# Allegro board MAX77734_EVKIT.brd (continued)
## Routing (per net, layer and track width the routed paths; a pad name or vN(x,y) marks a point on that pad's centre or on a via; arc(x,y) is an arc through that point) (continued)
UNNAMED_4_EKRESSMD_I17_2: length 1.6
  TOP w0.254: v1(15.5,63.17) 15.85,62.82 D100.K
  BOTTOM w0.254: R111.2 v1(15.5,63.17)
UNNAMED_4_EKRESSMD_I18_1: length 1.6
  BOTTOM w0.254: R109.1 14.45,61.28 14.18,61.02 U101.21
UNNAMED_4_EKRESSMD_I18_2: length 1.7
  TOP w0.254: v1(14.58,63.2) 14.58,63.14 14.28,62.83 D101.K
  BOTTOM w0.254: R109.2 14.45,63.06 v1(14.58,63.2)
UNNAMED_4_EKRESSMD_I87_1: length 2.5
  BOTTOM w0.254: R150.1 49.58,57.46 49.55,57.44 48.88,57.44 48.4,57.92 U107.3
UNNAMED_4_EKRESSMD_I109_1: length 1.9
  BOTTOM w0.254: R155.1 21.19,51.43 21.66,50.96 21.66,50.84 22.04,50.47 U100.36
UNNAMED_4_EKRESSMD_I113_1: length 1.7
  BOTTOM w0.254: R148.1 22.08,51.11 22.26,50.93 22.26,50.88 22.54,50.61 U100.37
UNNAMED_4_EKRESSMD_I153_1: length 1.8
  BOTTOM w0.254: U107.1 49.43,60.08 49.57,59.95 R135.1
UNNAMED_4_EKRESSMD_I154_1: length 1.8
  BOTTOM w0.254: R136.1 49.58,59.2 49.5,59.28 U107.2
UNNAMED_4_EKRESSMD_I171_2: length 1.7
  BOTTOM w0.254: U107.6 45.7,56.36 45.7,56.36 R143.2
UNNAMED_4_EKRESSMD_I174_1: length 2.5
  BOTTOM w0.381: R157.1 30.23,48.07 R156.2 30.26,48.06 30.96,48.06 31.33,48.43 U104.4
UNNAMED_4_EKRESSMD_I177_1: length 2.8
  BOTTOM w0.254: R159.1 20.69,57.08 R158.2 21.88,57.09 22.14,57.35 U102.4
UNNAMED_4_EKRESSMD_I190_2: length 2.7
  BOTTOM w0.254: U107.8 43.5,59.28 43.46,59.32 R151.2 42.88,60.22 R152.2
UNNAMED_4_EKRESSMD_I210_1: length 1.6
  BOTTOM w0.254: R133.1 47.3,55.96 47.3,55.97 U107.4
UNNAMED_4_LED_I7_B: length 1.7
  TOP w0.254: D102.K 20.38,62.83 20.41,62.86 R110.1
UNNAMED_4_LED_I189_B: length 38.8
  TOP w0.254: D103.K 63.05,43.5 v1(64.37,43.5) ; v1(41.96,57.49) 57.77,57.49 59.17,56.1 v1(64.37,56.1)
  INTERNAL3 w0.254: v1(64.37,56.1) v1(64.37,43.5)
  BOTTOM w0.254: v1(41.96,57.49) 41.96,58.1 41.98,58.12 R151.1
UNNAMED_4_MAX8512_I5_FB: length 2.6
  BOTTOM w0.254: U103.4 32.6,55.6 31.76,55.6 31.41,55.25 R160.2 31.29,55.25 R161.1
UNNAMED_6_CAPNP_I245_2: length 3.2
  BOTTOM w0.254: U209.1 56.62,25.49 C249.2 56.85,26.51 R285.2
UNNAMED_6_CAPNP_I341_2: length 5.2
  BOTTOM w0.203: U203.5 65.48,14.39 R252.2 65.3,15.42 C218.2 65.31,16.46 R254.1 64.96,16.81 R299.1
UNNAMED_6_CAPNP_I345_1: length 16
  INTERNAL3 w0.254: v1(67.95,14.54) 67.95,8.12 64.96,5.13 v1(64.96,3.93)
  BOTTOM w0.203: R253.1 67.2,15.41 C219.1 67.2,14.34 66.78,13.92 U203.7
  BOTTOM w0.254: R249.2 64.96,4.58 v1(64.96,3.93) ; C219.1 v1(67.95,14.54)
UNNAMED_6_CAPNP_I345_2: length 5.1
  BOTTOM w0.203: R300.2 66.45,16.77 R255.1 66.43,16.24 66.3,16.11 R253.2 66.3,15.41 C219.2 66.13,14.37 U203.6
UNNAMED_6_CAPNP_I357_2: length 4.2
  BOTTOM w0.203: R250.2 64.09,5.5 64.09,5.79 64.35,6.05 C251.2 65.08,6.39 65.12,6.36 65.54,6.36 66.13,6.95 U203.3
UNNAMED_6_EKCAPNP_I203_2: length 2.1
  BOTTOM w0.254: U205.10 48.74,11.62 C223.2
UNNAMED_6_EKCAPNP_I214_2: length 3.2
  BOTTOM w0.254: U209.8 48.75,25.49 48.44,25.8 C237.2 46.97,25.8 R286.2
UNNAMED_6_EKCAPNP_I332_2: length 18.9
  TOP w0.254: v1(70.06,26.95) 59.2,26.95 58.73,27.42 v1(57.49,27.42)
  INTERNAL3 w0.254: v1(57.49,27.42) 57.49,24.66 57.96,24.19 v1(57.96,22.15)
  BOTTOM w0.254: R259.1 v1(57.96,22.15)
  vias: v1(71.45,26.19) v1(72.74,26.18) v1(74.33,26.12)
UNNAMED_6_EKCAPNP_I355_1: length 3.9
  BOTTOM w0.203: R249.1 64.97,5.48 C216.1 65.84,5.48 66.78,6.42 U203.2
UNNAMED_6_EKCAPNP_I355_2: length 1
  BOTTOM w0.203: R248.1 65.8,4.57 C216.2
UNNAMED_6_EKCAPNP_I456_2: length 4.1
  BOTTOM w0.254: C235.2 49.62,18.39 U210.5 51.1,19.71 51.88,20.49 R279.1
UNNAMED_6_EKCAPNP_I459_2: length 7.1
  BOTTOM w0.254: C234.2 52.22,13.9 R280.1 51.64,14.97 51.08,15.52 51.08,16.48 U210.4 50.09,16.49 50.08,16.48 48.87,16.48 48.36,16.99 R277.2
UNNAMED_6_EKRESSMD_I207_2: length 1.9
  BOTTOM w0.254: U205.2 56.4,11.12 56.48,11.2 R214.2
UNNAMED_6_EKRESSMD_I222_2: length 2.1
  BOTTOM w0.254: U205.1 56,11.62 56.42,12.04 56.46,12.04 56.47,12.05 R283.2
UNNAMED_6_EKRESSMD_I340_2: length 8.9
  TOP w0.203: v1(70.35,18.79) 65.74,18.79 65.57,18.63 v1(64.99,18.63)
  BOTTOM w0.203: R254.2 64.98,18.61 v1(64.99,18.63) ; v1(70.35,18.79) 70.35,19.94 70.57,20.16 R258.1
UNNAMED_6_EKRESSMD_I347_1: length 3.7
  BOTTOM w0.203: U203.1 67.43,6.35 67.75,6.03 R251.1 67.74,5.47 R248.2
UNNAMED_6_EKRESSMD_I347_2: length 7.9
  BOTTOM w0.203: J206.1 72.14,8.36 68.35,4.58 R251.2
UNNAMED_6_EKRESSMD_I450_2: length 2.3
  BOTTOM w0.254: R213.2 57.04,9.3 56.36,9.98 56.3,9.98 56.16,10.12 U205.4
UNNAMED_6_EKRESSMD_I451_2: length 2.7
  BOTTOM w0.254: U205.5 55.15,9.09 55.87,8.38 R212.2
UNNAMED_6_EKRESSMD_I452_2: length 2.2
  BOTTOM w0.254: U209.6 48.65,24.19 48.43,23.98 R303.2
UNNAMED_6_EKRESSMD_I453_2: length 2.3
  BOTTOM w0.254: U209.5 48.78,23.54 48.43,23.19 47.94,23.19 R304.2
UNNAMED_6_EKRESSMD_I460_2: length 1.9
  BOTTOM w0.254: R280.2 53.12,15.02 54,15.9 U210.3
UNNAMED_6_EKRESSMD_I469_2: length 2.1
  BOTTOM w0.254: U205.3 56.68,10.62 R211.2
UNNAMED_6_EKRESSMD_I472_1: length 2
  BOTTOM w0.254: R210.1 49.06,10.97 49.22,11.12 U205.9
UNNAMED_6_EKRESSMD_I472_2: length 23.7
  TOP w0.254: v1(47.18,10.97) v1(63.15,10.97)
  INTERNAL3 w0.254: v1(63.15,10.97) v1(63.15,4.61)
  BOTTOM w0.254: v1(63.15,4.61) 64.08,4.61 R250.1 ; R210.2 v1(47.18,10.97)
UNNAMED_6_HEADER2P_I448_2: length 17.7
  INTERNAL3 w0.254: v1(71.28,11.02) 71.28,21.4 v1(70.43,22.25)
  BOTTOM w0.254: Q203.4 70.48,22.29 v1(70.43,22.25) ; R257.1 74.13,12.96 74.08,12.91 J206.2 72.82,10.9 72.7,11.02 v1(71.28,11.02)
UNNAMED_6_RESSMD_I363_2: length 5
  BOTTOM w0.254: R288.2 41.09,18.22 41.75,17.56 Q205.1 43.1,15.63 43.09,15.63 Q206.3
VADC: length 15.1
  INTERNAL3 w0.254: v1(45.2,25.76) v1(45.2,19.52)
  BOTTOM w0.254: R277.1 47.57,19.05 47.16,19.46 45.62,19.46 ; 45.62,19.46 45.55,19.52 v1(45.2,19.52) ; 45.62,19.46 Q205.2 41.44,19.46 41.09,19.12 R288.1 ; R286.1 v1(45.2,25.76)
VIO: length 157.9
  TOP w0.254: R9.1 62.97,39.2 62.97,39.2 v1(62,39.2) ; v1(44.8,55.16) v1(36.19,55.16)
  TOP w0.381: R6.1 29.82,62.94 30.3,62.46 v1(36.09,62.46) ; v1(41,34.55) 41.53,34.55 C5.2 41.58,34.55 60.93,34.55 61.06,34.68 v1(62,34.68) ; VIO.1 65.59,50.4 65.51,50.48 v1(62,50.48) v1(49.5,50.48) v1(36.14,50.48)
  TOP w0.508: J2.1 36.88,74.09 16.46,74.09 J101.1 J101.3 J101.5
  INTERNAL3 w0.203: v1(41,34.55) 40.08,34.55 v2(39.54,35.1)
  INTERNAL3 w0.254: v1(49.56,60.69) 49.56,59.04 49.5,58.98 v1(49.5,58.37) ; 36.14,55.18 36.16,55.16 v1(36.19,55.16)
  INTERNAL3 w0.381: v1(36.14,50.48) 36.14,62.53 ; 36.14,62.53 36.14,65.22 38.74,67.82 J2.1 ; 36.14,62.53 36.09,62.48 v1(36.09,62.46) ; v1(62,34.68) v1(62,39.2) v1(62,50.48) ; v1(49.5,58.37) v1(49.5,50.48)
  BOTTOM w0.254: R108.1 v1(49.56,60.69) ; R143.1 v1(44.8,55.16) ; R107.1 49.77,58.37 49.77,58.37 v1(49.5,58.37)
  BOTTOM w0.381: 47.91,61.18 U107.12 ; 47.91,61.18 48.41,60.69 v1(49.56,60.69) ; 47.91,61.18 48.65,61.91 C120.2
VL: length 55.2
  TOP w0.203: U1.A2 38.74,36.34 39.58,37.18 39.58,37.45 C3.2 v1(39.71,38.31)
  INTERNAL3 w0.381: v1(39.71,38.31) v1(39.71,65.98) ; VL.1 v1(21.1,65.98)
  BOTTOM w0.381: v1(39.71,65.98) 38.89,65.98 38.88,65.98 v1(21.1,65.98)
VUSB: length 196.8
  TOP w0.381: v1(48.15,15.59) 60.68,15.59 v1(63.11,13.16) v1(69.84,13.16)
  TOP w0.508: v1(47.9,41.42) v1(63.16,41.42) ; v1(12.13,61.84) 12.87,61.84 13.32,61.38 v1(26.39,61.38) 27.13,61.38 27.18,61.43 v1(36.95,61.43)
  TOP w0.635: v1(8.84,60.36) 9.85,60.36 11.33,61.84 v1(12.13,61.84)
  INTERNAL3 w0.381: v1(47.9,49.73) 47.9,49.35 47.9,49.35 ; v1(36.95,57.8) v1(36.95,49.73)
  INTERNAL3 w0.508: J100.1 49.84,66.39 47.9,64.45 v1(47.9,41.42) ; v1(63.16,41.42) 63.16,20.34 62.59,19.77 62.59,13.68 v1(63.11,13.16) ; v1(36.95,57.8) v1(36.95,61.43)
  INTERNAL3 w0.635: v1(8.84,60.36) 8.84,57.61 8.01,56.78 v1(8.01,54.63)
  BOTTOM w0.254: U203.8 68.27,12.81 68.64,13.18 C217.1 ; U103.3 34.4,55.68 34.07,56.01 34.07,56.84 34.21,56.98 U103.1 ; C110.2 v1(36.95,57.8) ; U101.19 13.18,60.75 12.66,61.27 C108.2 v1(12.13,61.84) ; Q205.3 45.3,16.58 45.29,16.58 Q206.1 47.05,15.87 R287.1
  BOTTOM w0.381: FB100.2 8.01,55.56 v1(8.01,54.63) C154.2 8.04,53.92 R115.1 8.04,52.18 ; v1(47.9,49.73) v1(36.95,49.73) 36.19,49.73 C112.2 35.49,49.74 35.48,49.73 U104.1 34.06,49.81 33.19,49.81 32.92,49.54 32.92,48.7 33.19,48.43 U104.3 ; U103.1 36.2,56.98 36.25,57.03 C110.2 ; R287.1 v1(48.15,15.59) ; C217.1 69.69,13.18 69.71,13.16 v1(69.84,13.16) ; U102.3 23.58,57.83 23.31,58.1 23.31,58.88 23.58,59.15 24.51,59.15 U102.1 25.53,59.13 25.55,59.11 C118.2 26.33,60.65 26.39,60.71 v1(26.39,61.38)
  BOTTOM w1.016: 8.04,52.18 8.04,50.43 6.78,49.18 5.36,49.18 5.35,49.19 J3.2

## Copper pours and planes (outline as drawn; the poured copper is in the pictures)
BATT on TOP: 3.43,20.95 3.68,20.7 24.51,20.7 35.81,32 35.81,33.78 36.2,34.16 37.08,34.16 37.21,34.29 37.21,34.67 35.31,34.67 27.81,27.18 21.34,27.18 19.18,25.02 3.43,25.02
BATTN on TOP: 3.81,10.79 3.81,19.18 4.7,20.07 15.37,20.07 15.49,19.94 15.49,17.14 9.14,10.79
CHGIN on TOP: 10.16,33.15 6.84,36.53 6.84,36.61 8.02,37.8 10.35,37.8 12.05,39.49 12.83,40.26 35.05,40.26 36.2,39.12 37.06,38.27 37.43,37.89 37.44,37.4 37.89,36.94 38.32,36.52 38.33,36.37 38.32,35.96 37.82,35.96 37.35,35.96 37.11,36.19 37.1,36.95 36.8,37.25 36.46,37.25 31.72,37.23 27.56,33.15
GROUND on TOP: 1.14,1.27 1.14,75.18 75.56,75.18 75.56,1.27 ; 19 cut-outs
GROUND on BOTTOM: 1.27,75.44 1.27,0.51 75.44,0.51 75.44,75.31 ; 14 cut-outs
GROUND on INTERNAL2: 0.89,75.18 0.89,0.89 75.95,0.89 75.95,75.18
INLDO on TOP: 42.45,2.8 42.45,12.07 39.01,15.51 39.01,31.86 39.03,31.88 39.02,32.81 39.02,33.39 39.22,33.57 39.45,33.79 39.45,34.52 39.56,34.62 39.67,34.51 39.67,33.19 39.66,31.37 39.66,31.37 39.66,29.98 40.65,28.99 41.83,27.81 41.88,21.47 46.71,16.63 46.71,2.85 46.66,2.8
LDO on TOP: 43.56,33.15 40.64,33.15 40.64,33.66 39.89,34.43 39.89,34.59 39.9,34.6 40.26,34.6 40.61,34.25 41.08,34.25 41.09,34.24 49.03,34.24 50.46,32.82 70.48,32.77 74.93,32.77 74.93,29.97 70.1,29.97 68.71,28.57 48.13,28.57
SYS on TOP: 40.35,32.24 40.35,29.91 41.7,29.9 41.69,31.63 41.1,32.23
SYS on TOP: 10.29,32.77 10.29,27.56 27.94,27.56 35.43,35.05 37.21,35.05 37.59,35.43 37.34,35.69 30.61,35.69 27.69,32.77
SYS on INTERNAL3: 27.69,32.77 30.73,35.81 38.99,35.81 38.98,33.72 40.48,32.25 42.13,32.25 42.16,20.42 40.78,20.38 26.83,20.41 19.76,27.48 11.18,27.56 11.18,32.77
UNNAMED_6_EKCAPNP_I332_2 on TOP: 69.67,24.94 69.67,27.56 71.26,27.56 72.36,28.66 72.39,29.59 75.18,29.59 75.16,24.94
UNNAMED_6_EKCAPNP_I332_2 on BOTTOM: 71.88,29.84 71.25,29.21 71.25,28.19 70.87,27.81 70.23,27.81 69.72,27.3 69.72,23.24 75.18,23.24 75.18,29.84
UNNAMED_6_EKRESSMD_I340_2 on BOTTOM: 71.63,22.86 71.37,22.73 71.37,15.49 74.93,15.49 74.93,22.86

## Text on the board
Ref Des/Silkscreen Top: GND | BATTN | CHGIN | VUSB | GUI | LDO | INCREASE | 3.3V | TEMP | VIO | 1.8V | RES | THM | NTC | POT | POKLDO | +3.3V | PMLDO | SCL1 | SDA1 | PMLDO1 | NIRQ1 | SW2 | SW1 | NEN | www.maximintegrated.com | 1-408-601-1000 | LB05/17 | MAX77734EV KIT | REVB
DIMENSION: 1 OZ,0.0014" MIN | 0.5 OZ,0.007" | TBD | NOTES: | FINISH: | TESTING: | MISCELLANEOUS: | TOOLING: | 15.  CHECK ALL THAT APPLY | 16.  VENDOR LOGO & DATE CODE REQUIRED IN INK ON BOTTOM SIDE ONLY. DATE CODE FORMAT MUST BE YYWW ONLY | 17.  FINAL ELECTRICAL TEST TO BE PERFORMED USING PROVIDED IPC-D-356A NETLIST OR ODB++ FORMAT FILE. | 18.  A TIME DOMAIN REFLECTOMETER REPORT FOR EACH IMPEDANCE CONTROLLED LAYER AND A CERTIFICATE | 24.  THIEVING: | 23.  FINISHED SURFACE CONTACTS AND FILLED VIAS TO BE FREE OF ANY PITS. SCRATCHES PROBE MARKS | 19.  FOR BLIND AND BURIED VIA INFORMATION REFER TO DRILL CHART. | 21.  ALL MICRO-VIAS LESS THAN 0.006 INCHES FHS WILL BE PLATED SHUT WITH COPPER, UNLESS OTHERWISE SPECIFIED. | 22.  FOR VIA SIZES XX.XX INCH USE NON CONDUCTIVE VIA FILL AND CAP | 13.  DRILL SIZES ARE FINISHED HOLE SIZES. ALL HOLES SHALL BE LOCATED WITHIN .005 DTP. | 14.  CHECK ALL THAT APPLY | 25.  PEMNUT | 9.  ALL TRACES FILLETED OPTION TO ENHANCE RELIABILITY AT PAD JUNCTIONS | 10.  LAYER TO LAYER REGISTRATIONS SHALL BE WITHIN .003 INCHES. | MATERIAL: | 11.  FINISHED COPPER WEIGHT/THICKNESS: | 12.  CHECK ALL THAT APPLY | 8.  IF STATED IN THE LAMINATION DIAGRAM, THE DIELECTRIC THICKNESS OF ANY | 1.  DIMENSIONS ARE IN INCHES (EXCEPT WHERE NOTED). | 3.  THE PCB SHALL BE FABRICATED TO IPC-6012, TYPE X, CLASS 2. | 4.  BOARD MATERIAL & CONSTRUCTION SHALL MEET THE REQUIREMENTS OF UL796 | 5.  OVERALL BOARD THICKNESS REFER TO LAMINATION DIAGRAM. TOLERANCE APPLIES | 6.  BOW & TWIST NOT TO EXCEED 0.0075 IN. (0.75%) PER LINEAR INCH. | 7.  PHOTO ETCH CIRCUITRY PER ENCLOSED GERBER RS274X OR ODB++ FORMAT FILE. | 2.  BOARD MATERIAL: | ( )  APPLY SILKSCREEN TO TOP SIDE USING A NON-CONDUCTIVE, WHITE EPOXY | ( )  OTHER ________________________ | (x)  APPLY SILKSCREEN TO BOTH SIDES USING A NON-CONDUCTIVE, WHITE EPOXY | (x)  GREEN SOLDERMASK OVER BARE COPPER/BARE GOLD (BOTH SIDES) WITH LIQUID PHOTO IMAGEABLE INK (LPI) | ( )  GREEN TAIYO PSR-4000 | (X)  REFER TO LAMINATION DIAGRAM FOR FINISHED COPPER WEIGHT/THICKNESS REQUIREMENTS. | ( )  FINGERS TO BE GOLD PLATED. | ( )  FINISH CONDUCTOR SURFACES: IMMERSION GOLD, 2-5 MICRO INCHES OVER | (X)  SUPPLIER MAY ADD THIEVING TO COMPENSATE FOR LOW COPPER DENSITY AREAS ON THIS DESIGN. | ( )  SUPPLIER MAY NOT ADD THIEVING TO COMPENSATE FOR LOW COPPER DENSITY AREAS ON THIS DESIGN. | ( )  NON-CONDUCTIVE EPOXY. FILL AND CAP ALL 0.XXXX INCH DRILLED VIAS. | ( )  SILVER. FILL AND CAP ALL 0.XXXX INCH DRILLED VIAS. | ( )  ELECTODEPOSITED HARD GOLD PLATE, TYPE 1 (99.7% MIN GOLD), GRADE C | (X) LEAD FREE AND RoHS COMPLIANT OR EQUIVALENT LEAD FREE PLATING | (REQUIRED UNLESS OTHERWISE SPECIFIED IN QUOTE) | THE PCB SHALL HAVE A VERIFICATION STAMP. | OF COMPLIANCE SHALL BE PROVIDED BY VENDOR AT TIME OF SHIPMENT. | ( )  PEMNUT TO BE INSTALLED BY SUPPLIER | ( )  PEMNUT NOT TO BE INSTALLED BY SUPPLIER | OR OTHER DEFORMITIES THAT COULD EFFECT THE APPERANCE AND PERFORMACE OF THE CONTACT | SURFACE. CONTACTS ARE TO BE AS FLAT AS POSSIBLE. NOT TO EXCEED +/- 0.001" OF FLATNESS. | (x)  FINISH CONDUCTOR SURFACES: IMMERSION GOLD, 3-8 MICRO INCHES OVER | ( )  FILLETED | (X)  NOT FILLETED | SO AS TO HINDER PROPER SOLDER WICKING. | (X)  ISOLA 370HR OR EQUIVALENT | ( )  NELCO-4000-13 | ( )  MEGTRON 6 | ( )  ROGERS 4350B | ( )  ROGERS 4003C | MINIMUM BARREL PLATING OF .001 IN. PLATED HOLES SHALL NOT BE ROUGH OR IRREGULAR | ( )  ISOLA-FR408HR OR EQUIVALENT | CONTROLLED IMPEDANCE LAYER IS FOR REFERENCE ONLY. FINAL ACCEPTANCE | SHALL BE DETERMINED BY THESE LAYERS HAVING A CHARACTERISTIC | IMPEDANCE OF +/-10% OHMS AS STATED IN THE LAMINATION DIAGRAM. THE | VENDOR CAN MAKE ADJUSTMENTS AS LONG AS THE STATED IMPEDANCE AND | OVERALL BOARD THICKNESS IS MAINTAINED. ANY ADJUSTMENT MADE TO TRACE | WIDTH OR SPACING MUST HAVE PRIOR WRITTEN APPROVAL FROM MAXIM. | WHERE SPACING PERMITS. | LEGEND TO LEGEND +/- 0.007 INCHES | WORKMANSHIP SHALL CONFORM TO IPC-A-600, CLASS 2, CURRENT REVISIONS. | WITH FLAMMABILITY RATING OF 94V-O. | AFTER ALL LAMINATION AND PLATING PROCESSES. IT IS TO BE MEASURED FROM | TOP PCB METAL TO BOTTOM PCB METAL UNLESS OTHERWISE SPECIFIED. | BOW & TWIST SHOULD BE MEASURED PER IPC-TM-650, METHOD 2.4.22. | DRILL LOCATION AND SIZE CONTROLLED BY EXCELLON CNC DRILL FILE. | UNLESS OTHERWISE SPECIFIED | BASED INK PER ARTWORK. | PER ARTWORK. | THE STARTING COPPER WEIGHT/THICKNESS CAN VARY AS LONG AS THE FINISHED COPPER | WEIGHT/THICKNESS IS NOT LESS THAN THE SPECIFIED VALUE. UNLESS OTHERWISE SPECIFIED. | (KNOOP HARDNESS 130-200), CLASS 1 (50-100 MICRO INCHES THICK) IN ACCORDANCE WITH MIL-G-45204C. | GENERAL SURFACING REQUIREMENTS MUST MEET ANSI/IPC-A-600(CURRENT REV) SECTION 4.0, | CLASS 3 (50-100 MICROINCHES THICK) OVER ELECTRODEPOSITED NICKEL PLATE | IN ACCORDANCE WITH ANSI/IPC-A-600D, SECTION 4.0, CLASS 3 (200-600 MICROINCHES THICK). | 118-236 MICRO INCHES MINIMUM OF ELECTROLESS NICKEL. | 100 MICRO INCHES MINIMUM OF ELECTROLESS NICKEL. | (USE CHECKED ITEMS FOR MATERIAL) | (USE CHECKED ITEMS FOR PLATING) | (USE CHECKED ITEMS FOR TOOLING) | UNLESS OTHERWISE SPECIFIED: | LAYER | NUMBER | THE FINISHED PCB THICKNESS TO BE: | 1 | 2 | 3 | 4 | TOP | INTERNAL2 | INTERNAL3 | BOTTOM | NAME | COPPER THICKNESS | (OZ,INCH) | LAMINATION DIAGRAM | DIELECTRIC | THICKNESS (in.) | 0.062" +/-0.010" | ISOLA 370HR/EQUIVALENT | FOIL | MATERIAL | NOT TO SCALE | TEMPLATE REV 1.7 | TOLERANCES UNLESS OTHERWISE SPECIFIED | +/- | FRACTIONS | SEE NOTES | .XXX +/- .005 | .XX +/- .01 | DECIMALS | ANGLES | THE INFORMATION CONTAINED IN THIS DOCUMENT | IS PROPRIETARY TO MAXIM. THE INFORMATION IN | THIS DOCUMENT IS NOT TO BE SHOWN, REPRODUCED, | OR DISCLOSED TO ANYONE OUTSIDE OF MAXIM | WITHOUT PRIOR WRITTEN PERMISSION FROM MAXIM. | DRAWN BY: | CHECKED BY:ERIC RULE | APPR. BY: | LAKSHMI BHUJ | DATE: | DATE:05/10/2017 | 05/10/2017 | SIZE | E | DRAWING NO. | SHEET 1 OF 1 | REV | B | DESCRIPTION | REVISIONS | APPROVED | DATE | TITLE: | A | RELEASE | MAX77734 EVALUATION BOARD | FABRICATION DWG. | XX-XXXXXX-XX
User.25: FIGURE | SIZE | 5.0 | 8.0 | 37.4 | 39.37 | 45.28 | 70.87 | 125.0 | 35.43 | 41.34x25.59 | 51.18x27.56 | TOLERANCE | +3.0/-3.0 | +3.0/-6.0 | PLATED | NON-PLATED | ALL UNITS ARE IN MILS | QTY | 12 | 273 | 5 | 21 | 40 | 8 | 4 | 2 | NOTES | DRILL CHART: TOP to BOTTOM
